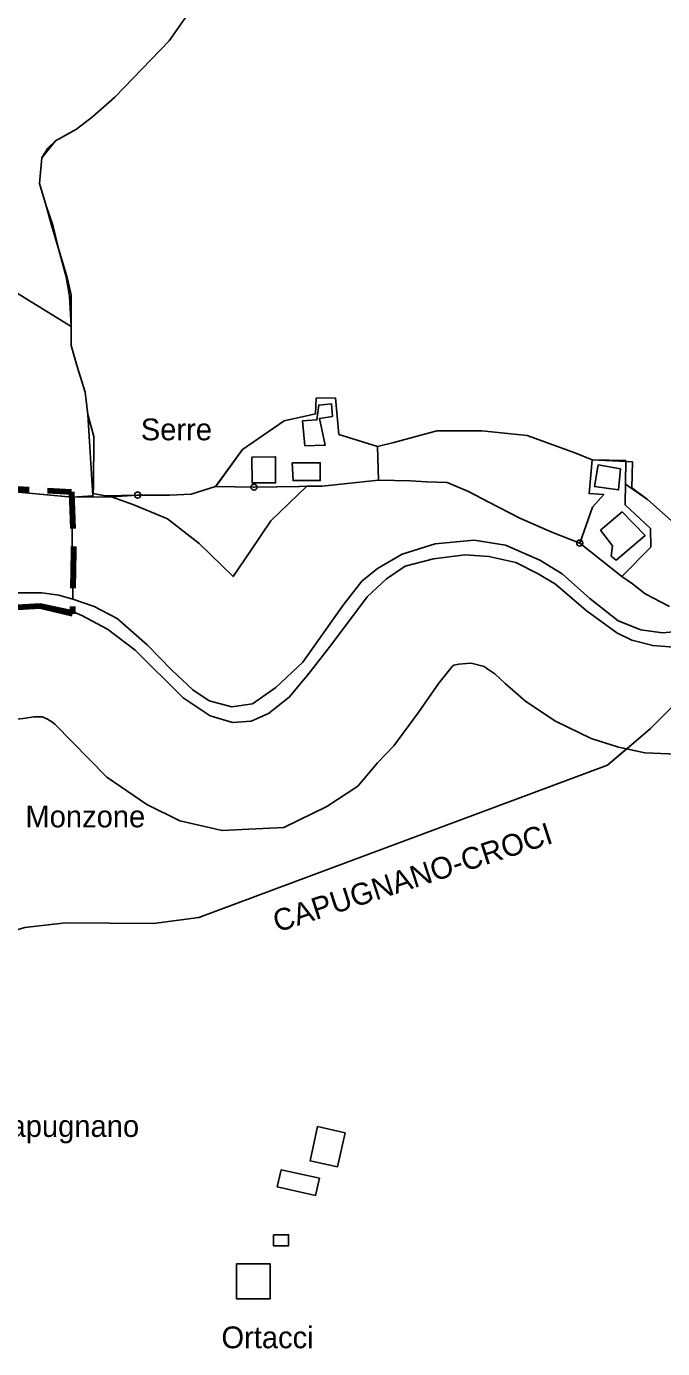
# Model space of a CAD drawing. Extents: x 652791 to 656927, y 889884 to 892405.
# Drawn here: x 656147 to 656439, y 891189 to 891796 of the extents above; entities that cross this region are included whole.
import ezdxf
from ezdxf.enums import TextEntityAlignment as Align

# ---------------------------------------------------------------- set-up
doc = ezdxf.new("R2010")
doc.units = 0
doc.header["$LTSCALE"] = 5.6
doc.header["$PDMODE"] = 32
doc.header["$PDSIZE"] = 2.8
doc.linetypes.add('MEDIUM_DASHED', pattern=[4.5, 3, -1.5])
for name, color, linetype, lineweight in [('2', 7, 'Continuous', 25), ('30', 7, 'Continuous', 25), ('35', 7, 'Continuous', 25), ('37', 7, 'Continuous', 25), ('55', 7, 'Continuous', 25), ('6', 7, 'Continuous', 25), ('7', 7, 'MEDIUM_DASHED', 100), ('9', 7, 'Continuous', 25)]:
    doc.layers.add(name, color=color, linetype=linetype, lineweight=lineweight)
doc.layers.add('60', color=7, linetype='Continuous')

msp = doc.modelspace()

# ---------------------------------------------------------------- linework, layer by layer
at = {"layer": '2'}
for points in [[(656251.69, 891584.17), (656282.99, 891584.67), (656308.89, 891587.35), (656308.38, 891602.9), (656290.69, 891608.37), (656289.08, 891625.12), (656280.2, 891624.95), (656279.86, 891617.77), (656265.51, 891614.69), (656246.38, 891601.53), (656234.08, 891584.44)], [(656273.88, 891614.69), (656275.08, 891603.07), (656284.3, 891603.41), (656281.74, 891615.72), (656287.71, 891616.57), (656287.2, 891622.38), (656281.4, 891621.87), (656280.54, 891615.03)], [(656250.65, 891597.94), (656250.82, 891586.15), (656261.58, 891586.15), (656261.58, 891598.11)], [(656269.27, 891595.38), (656269.61, 891587.18), (656282.08, 891587.18), (656282.08, 891595.38)], [(656401.27, 891558.49), (656420.54, 891543.12), (656433.94, 891556.63), (656433.72, 891565.24), (656422.07, 891576.03), (656422.39, 891596.41), (656406.93, 891596.73), (656405.51, 891581.26), (656412.27, 891580.82), (656407.15, 891574.94)], [(656409.71, 891594.48), (656408.1, 891584.43), (656419.07, 891582.91), (656420, 891592.54)], [(656410.84, 891564.39), (656420.8, 891572.83), (656431.26, 891562.02), (656417.93, 891550.71), (656415.74, 891552.57), (656416.24, 891557.3)]]:
    msp.add_lwpolyline(points, close=True, dxfattribs=at)
at = {"layer": '30'}
msp.add_lwpolyline([(656033.93, 891681.09), (656028.23, 891706.07), (656024.27, 891730.81), (656023, 891738.57), (656033.49, 891729.45), (656042.16, 891722.94), (656065.31, 891710.28), (656089.17, 891699.79), (656118.1, 891685.67), (656140.89, 891674.46), (656167.75, 891657.93), (656167.75, 891649.15), (656170.42, 891639.61), (656174.23, 891627.77), (656175.38, 891617.47), (656177.69, 891580.17), (656168.2, 891579.6), (656146.57, 891581.6)], dxfattribs=at)
at = {"layer": '35'}
msp.add_line((656198.23, 891580.51), (656186.31, 891579.76), dxfattribs=at)
for points in [[(656047.32, 891834.46), (656023, 891756.2), (656023, 891738.57), (656033.49, 891729.45), (656042.16, 891722.94), (656064.51, 891710.71), (656089.17, 891699.79), (656140.89, 891674.46), (656167.75, 891657.93), (656167.75, 891657.93), (656166.96, 891671.83), (656165.46, 891680.68), (656162.03, 891693.05), (656158.68, 891704.42), (656156.3, 891713.28), (656153.25, 891723.59), (656154.2, 891735.29), (656156.98, 891739.83), (656160.57, 891743.21), (656170.25, 891748.49), (656177.5, 891754.21), (656187.83, 891763.23), (656212.68, 891789), (656236.47, 891823.03)], [(656401.27, 891558.49), (656388.45, 891563.53), (656373.75, 891569.91), (656359.54, 891577.26), (656350.23, 891582.17), (656340.43, 891586.34), (656330.87, 891586.58), (656323.52, 891587.07), (656308.89, 891587.35), (656282.99, 891584.67), (656275.98, 891584.56)], [(656251.69, 891584.17), (656234.08, 891584.44), (656222.91, 891580.94), (656212.94, 891580.51), (656198.23, 891580.51)], [(656275.98, 891584.56), (656259.46, 891568.7), (656250.27, 891555.09), (656242.05, 891543.13), (656226.49, 891558.32)], [(656226.49, 891558.32), (656242.05, 891543.13), (656250.27, 891555.09), (656259.46, 891568.7), (656275.98, 891584.56), (656272.24, 891584.5), (656251.69, 891584.17)], [(656186.31, 891579.75), (656168.2, 891579.6), (656168.12, 891556.06), (656168.45, 891532.73)], [(656186.31, 891579.76), (656196.53, 891575.99), (656211.96, 891569.69), (656226.49, 891558.32)], [(656226.49, 891558.32), (656211.96, 891569.69), (656196.53, 891575.99), (656186.32, 891579.75), (656186.31, 891579.75)], [(656168.45, 891532.73), (656178.27, 891529.33), (656188.91, 891523.83), (656202.65, 891511.81), (656213.98, 891500.13), (656223.59, 891491.2), (656231.15, 891486.04), (656241.45, 891483.29), (656251.06, 891484.67), (656261.71, 891492.23), (656274.07, 891503.91), (656292.61, 891530.02), (656301.19, 891541.01), (656308.4, 891546.85), (656319.73, 891553.38), (656334.84, 891558.19), (656352.7, 891559.91), (656367.12, 891557.5), (656382.91, 891550.63), (656393.22, 891544.45), (656405.92, 891533.11), (656418.97, 891522.8), (656429.27, 891518.69), (656439.23, 891517.31), (656454.68, 891518.69)], [(656442.51, 891529.38), (656431.26, 891535.26), (656425.45, 891539.75), (656420.54, 891543.12), (656401.27, 891558.49)], [(656444.38, 891510.79), (656434.76, 891511.47), (656425.15, 891513.88), (656418.28, 891517.31), (656404.21, 891527.62), (656390.13, 891539.65), (656382.23, 891544.46), (656371.93, 891549.61), (656359.57, 891552.36), (656348.58, 891553.04), (656334.16, 891551.33), (656321.11, 891547.89), (656312.53, 891542.05), (656303.6, 891533.81), (656287.8, 891512.5), (656276.47, 891498.07), (656267.89, 891487.77), (656258.28, 891480.21), (656250.38, 891476.77), (656241.79, 891476.08), (656231.49, 891479.17), (656219.1, 891487.46), (656197.15, 891509.4), (656184.42, 891518.93), (656172.58, 891525.28), (656166.51, 891527.84)], [(656166.51, 891527.84), (656154.23, 891530.47), (656122.64, 891528.13), (656116.65, 891525.08)], [(656422.82, 891464.06), (656433.72, 891473.33), (656483.94, 891523.47)], [(656217.59, 891430.94), (656237, 891426.53), (656249.34, 891427.21), (656265.34, 891428.01), (656285.18, 891437.55), (656299.29, 891446.97), (656308.37, 891457.56), (656315.94, 891465.5), (656327.12, 891480.54), (656336.51, 891494.21), (656342.69, 891501.8), (656343.43, 891502.42), (656345.81, 891502.91), (656349.22, 891503.24), (656350.71, 891503.37), (656352.01, 891503.2), (656357.3, 891501.85), (656359.07, 891500.65), (656362.23, 891498.43), (656367.03, 891494.07), (656376.54, 891485.85), (656390.16, 891476.76), (656406.48, 891468.84), (656418.98, 891464.86), (656422.82, 891464.06)], [(656217.59, 891430.94), (656237, 891426.53), (656249.34, 891427.21), (656265.34, 891428.01), (656285.18, 891437.55), (656299.29, 891446.97), (656308.37, 891457.56), (656315.94, 891465.5), (656327.12, 891480.54), (656336.51, 891494.21), (656342.69, 891501.8), (656343.43, 891502.42), (656345.81, 891502.91), (656349.22, 891503.24), (656350.71, 891503.37), (656352.01, 891503.2), (656357.3, 891501.85), (656359.07, 891500.65), (656362.23, 891498.43), (656367.03, 891494.07), (656376.54, 891485.85), (656390.16, 891476.76), (656406.48, 891468.84), (656418.98, 891464.86), (656422.82, 891464.06), (656422.77, 891464.02)], [(656422.77, 891464.02), (656413.94, 891456.5), (656226.36, 891386.67), (656205.54, 891383.87), (656165.13, 891384.18), (656146.48, 891382.01), (656108.81, 891370.86), (656095.2, 891368.25), (656091.47, 891367.73), (656081.59, 891365.81), (656087.34, 891377.65), (656090.3, 891385.37), (656088.48, 891398.33), (656078.47, 891422.3), (656074.29, 891435.57), (656072.29, 891443.27), (656071.65, 891452.77), (656073.24, 891465.01), (656081.57, 891475.88), (656089.03, 891484.77), (656095.78, 891483.3), (656118.99, 891471.57)], [(656118.99, 891471.57), (656129.71, 891474.95), (656137.93, 891477.26), (656145.68, 891477.91), (656150.56, 891478.82)], [(656118.99, 891471.57), (656129.71, 891474.95), (656137.93, 891477.26), (656145.68, 891477.91), (656150.56, 891478.82)], [(656150.56, 891478.82), (656154.66, 891478.69), (656154.91, 891478.59), (656156.9, 891477.64), (656158.85, 891476.4), (656160.19, 891475.34), (656184.15, 891451.05), (656202.46, 891438.51), (656217.59, 891430.94)], [(656150.56, 891478.82), (656154.66, 891478.69), (656154.91, 891478.59), (656156.9, 891477.64), (656158.85, 891476.4), (656160.19, 891475.34), (656184.15, 891451.05), (656202.46, 891438.51), (656217.59, 891430.94)]]:
    msp.add_lwpolyline(points, dxfattribs=at)
for p in [(656198.23, 891580.51), (656251.69, 891584.17), (656401.27, 891558.49)]:
    msp.add_point(p, dxfattribs=at)
at = {"layer": '37'}
for points in [[(656239.58, 891884.9), (656251.8, 891878.19), (656258.02, 891872.19), (656260.02, 891868.63), (656260.47, 891863.74), (656257.36, 891857.51), (656236.47, 891823.03), (656212.68, 891789), (656187.83, 891763.23), (656177.5, 891754.21), (656170.25, 891748.49), (656160.57, 891743.21), (656154.2, 891735.29), (656153.25, 891723.59), (656156.3, 891713.28), (656159.36, 891704.5), (656162.03, 891693.05), (656165.84, 891680.45), (656167.75, 891672.44), (656167.75, 891657.93)], [(656167.75, 891657.93), (656167.75, 891649.15), (656170.42, 891639.61), (656174.23, 891627.77), (656175.38, 891617.47), (656178.1, 891607.41), (656178.04, 891584.27), (656177.78, 891581.2), (656183.34, 891580.26), (656198.23, 891580.51), (656212.94, 891580.51), (656222.91, 891580.94), (656234.08, 891584.44)], [(656234.09, 891584.44), (656246.39, 891601.53), (656265.52, 891614.69), (656279.87, 891617.77), (656280.21, 891624.95), (656289.09, 891625.12), (656290.7, 891608.37), (656308.39, 891602.9)], [(656308.39, 891602.9), (656315.93, 891604.71), (656335.61, 891610.04), (656356.28, 891610.04), (656377.18, 891607.94), (656399.51, 891599.77), (656406.94, 891596.73), (656422.4, 891596.41)], [(656422.4, 891596.41), (656422.23, 891585.59), (656432.3, 891578.53), (656444.62, 891567.63)], [(656422.82, 891464.05), (656413.94, 891456.5), (656226.36, 891386.67), (656205.54, 891383.87)], [(656445.81, 891461.61), (656431.13, 891462.3), (656422.82, 891464.05)], [(656205.54, 891383.87), (656165.13, 891384.18), (656146.48, 891382), (656108.81, 891370.85), (656110.65, 891371.26), (656096.25, 891317.09), (656083.35, 891320.35), (656080.48, 891310.57), (656053.24, 891316.44), (656039.97, 891320.62), (656038.81, 891314.63), (656031.74, 891315.79), (656019.56, 891319.7), (656021.84, 891328.41), (656025.35, 891328.76)]]:
    msp.add_lwpolyline(points, dxfattribs=at)
at = {"layer": '55'}
msp.add_line((656444.62, 891567.62), (656432.3, 891578.53), dxfattribs=at)
for points in [[(656432.3, 891578.53), (656425.23, 891583.86), (656425.42, 891595.82), (656406.93, 891596.73), (656399.5, 891599.77), (656377.17, 891607.94), (656356.28, 891610.03), (656335.61, 891610.03), (656315.93, 891604.71), (656308.38, 891602.9)], [(656308.38, 891602.9), (656308.89, 891587.35), (656282.99, 891584.67), (656275.98, 891584.56), (656259.46, 891568.7), (656250.27, 891555.09), (656242.05, 891543.13), (656226.49, 891558.32), (656211.96, 891569.69), (656196.53, 891575.99), (656186.31, 891579.75), (656168.2, 891579.6)], [(656168.2, 891579.6), (656146.57, 891581.6), (656146.52, 891583.98)], [(656150.56, 891478.82), (656154.66, 891478.69), (656154.91, 891478.59), (656156.9, 891477.64), (656158.85, 891476.4), (656160.19, 891475.34), (656184.15, 891451.05), (656202.46, 891438.51), (656217.59, 891430.94), (656237, 891426.53), (656249.34, 891427.21), (656265.34, 891428.01), (656285.18, 891437.55), (656299.29, 891446.97), (656308.37, 891457.56), (656315.94, 891465.5), (656327.12, 891480.54), (656336.51, 891494.21), (656342.69, 891501.8), (656343.43, 891502.42), (656345.81, 891502.91), (656349.22, 891503.24), (656350.71, 891503.37), (656352.01, 891503.2), (656357.3, 891501.85), (656359.07, 891500.65), (656362.23, 891498.43), (656367.03, 891494.07), (656376.54, 891485.85), (656390.16, 891476.76), (656406.48, 891468.84), (656418.98, 891464.86), (656431.13, 891462.3), (656445.81, 891461.61)], [(656118.99, 891471.57), (656129.71, 891474.95), (656137.93, 891477.26), (656145.68, 891477.91), (656150.56, 891478.82)]]:
    msp.add_lwpolyline(points, dxfattribs=at)
at = {"layer": '6'}
for points in [[(656280.91, 891290.64), (656277.42, 891275.02), (656289.98, 891272.21), (656293.47, 891287.83)], [(656264.12, 891270.86), (656262.37, 891263.05), (656279.94, 891259.11), (656281.69, 891266.93)], [(656260.59, 891241), (656267.59, 891241), (656267.59, 891236), (656260.59, 891236)], [(656243.63, 891227.63), (656259.13, 891227.63), (656259.13, 891211.63), (656243.63, 891211.63)]]:
    msp.add_lwpolyline(points, close=True, dxfattribs=at)
at = {"layer": '7'}
msp.add_lwpolyline([(656129, 891580.08), (656131.73, 891584.05), (656167.86, 891582.06), (656168.86, 891554.58), (656168.36, 891526.1), (656153.52, 891529.58), (656142.9, 891528.92), (656131.29, 891528.04)], dxfattribs=at)
at = {"layer": '9'}
for points in [[(656099.86, 891562.27), (656112.2, 891562.81), (656120.71, 891554.02), (656128.51, 891572.64), (656133.47, 891582.81), (656168.2, 891579.6), (656168.12, 891556.06), (656168.45, 891532.73)], [(656168.45, 891532.73), (656162.02, 891534.55), (656154.23, 891535.73), (656142.71, 891535.73), (656116.47, 891536.07), (656112.24, 891537.93), (656103.77, 891546.23), (656102.08, 891551.32), (656101.4, 891556.74), (656099.86, 891562.27)]]:
    msp.add_lwpolyline(points, dxfattribs=at)

# ---------------------------------------------------------------- texts
at = {"layer": '60'}
for s, p in [('Serre', (656216.06, 891605.69)), ('Monzone', (656174.23, 891428.03)), ('Capugnano', (656164.37, 891285.92)), ('Ortacci', (656257.91, 891188.92))]:
    msp.add_text(s, height=10, dxfattribs=at).set_placement(p, align=Align.CENTER)
msp.add_text('CAPUGNANO-CROCI', height=10, rotation=17.956, dxfattribs=at).set_placement((656325.96, 891400.35), align=Align.CENTER)

doc.saveas('drawing.dxf')
